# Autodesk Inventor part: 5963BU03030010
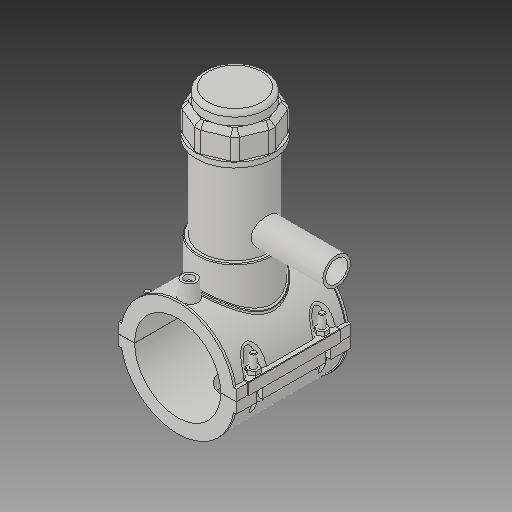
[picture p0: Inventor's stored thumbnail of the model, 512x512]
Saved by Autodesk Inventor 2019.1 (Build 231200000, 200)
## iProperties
Created: 2017-07
Part Number: 5963BU03030010
Material: Generic
Description: PLASSON TAPPING SADDLE 3''IPS x 1''CTS
Document SubType Name: Modeling
Designer: KIM
Mass: 1712.7 g
Surface Area: 2671.49 cm^2
Volume: 1712.7 cm^3
Density: 1 g/cm^3
Appearance: Default
Author: KIM
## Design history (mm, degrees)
derived "5963B.ipt"
feature "Solid1::5963B.ipt"
feature "Solid2::5963B.ipt"
feature "Solid4::5963B.ipt"
feature "Solid5::5963B.ipt"
tag "TaggingFeature1"
body "Solid1"
body "Solid2"
other parameters: "d0" = 88.7, "d2" = 120.904, "d3" = 22.175, "d4" = 118.11, "d5" = 0, "d6" = 0.1, "d8" = 0, "d19" = 6, "d20" = 6, "d21" = 70.866, "d23" = 0, "d24" = 35.433, "d26" = 0, "d29" = 3, "d30" = 29.56667, "d31" = 6, "d32" = 0, "d33" = 0, "d34" = 0.6, "d40" = 59.9612, "d41" = 79.83, "d43" = 0, "d45" = 0, "d47" = 128.521, "d70" = 15, "d72" = 0, "d73" = 6, "d75" = 5, "d76" = 0, "d77" = 4.435, "d78" = 74.35, "d79" = 15, "d80" = 47.244, "d82" = 5 deg, "d84" = 4, "d85" = 14, "d86" = 0, "d87" = 3, "d88" = 0, "d89" = 1, "d90" = 1, "d91" = 94.488, "d92" = 0, "d93" = 0.5, "d94" = 46.68421, "d96" = 117.6162, "d97" = 2.3622, "d98" = 0, "d102" = 0.887, "d120" = 140 deg, "d121" = 24.228, "d122" = 20 deg, "d123" = 230.62, "d124" = 69.186, "d126" = 0, "d143" = 91.361, "d145" = 20.46923, "d149" = 1.3305, "d150" = 22.51615, "d153" = 118.11, "d154" = 0, "d156" = 57.655, "d157" = 160 deg, "d159" = 5.322, "d161" = 1.3305, "d162" = 70.866, "d163" = 0, "d164" = 44.35, "d167" = 8.87, "d168" = 56.24878, "d170" = 3.2805, "d172" = 0, "d173" = 1, "d175" = 44.35, "d176" = 20 deg, "d177" = 6.209, "d178" = 26.61, "d180" = 0, "d183" = 10.644, "d184" = 4.9672, "d185" = 38.38575, "d186" = 38.38575, "d187" = 57.655, "d188" = 7.983, "d189" = 6.209, "d190" = 0, "d191" = 86.4825, "d193" = 6.1236, "d194" = 4.13385, "d195" = 90 deg, "d197" = 0, "d199" = 0, "d200" = 13.305, "d202" = 0, "d203" = 177.038, "d204" = 75.8385, "d205" = 55.881, "d206" = 67.8555, "d207" = 132.7785, "d208" = 138.08964, "d209" = 164.64534, "d210" = 68.6538, "d211" = 79.83, "d212" = 63.864, "d213" = 45.7191, "d216" = 0, "d217" = 8.87, "d218" = 4.435, "d219" = 0.887, "d222" = 88.7, "d224" = 0, "d230" = 5.322, "d233" = 6, "d236" = 60.452, "d237" = 35.433, "d238" = 6.02433, "d240" = 35.433, "d241" = 35.433, "d242" = 35.433, "d243" = 6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
